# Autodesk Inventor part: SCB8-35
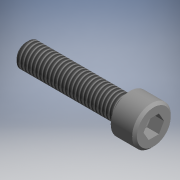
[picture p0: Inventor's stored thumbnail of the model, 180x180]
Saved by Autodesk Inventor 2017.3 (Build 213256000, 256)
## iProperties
Part Number: SCB8-35
Material: Generic
Catalog Web Link: www.cadenas.de
Description: SCB-Hexagon Socket Head Cap Screws - Stainless Steel
Vendor: MISUMI
Document SubType Name: Modeling
Designer: partserver
Manufacturer: MISUMI
Mass: 2.66941 g
Surface Area: 15.2394 cm^2
Volume: 2.66941 cm^3
Density: 1 g/cm^3
Appearance: PSOLRGB-175-175-175
Category: PARTsolutions
Company: MISUMI
Title: SCB8-35
Author: Cadenas PARTsolutions
Comments: Hexagon Socket Head Cap Screws - Stainless Steel
PSOL_IDENT_0: {$CADENAS_DATA\23d-libs\misumi\metric\27_screws_nuts\scb_fa.prj},154 {VTYP=3D},{NB=SCB8-35},{LINA=SC
PSOL_IDENT_1: B8-35},{NN=SCB},{DATE=03.06.2021 03:35:43},{GEOMDATE=23.02.2012 00:00:00},{VERSION=},{LINEID=110},{W
PSOL_IDENT_2: BVAR=L},{WBNUMERIC=L}  {NB=SCB8-35},{LINA=SCB8-35},{KT=DUMMY},{PN=SCB8-35},{MAT=SUSXM7(30430 Stainle
PSOL_IDENT_3: ss Steel)},{SC=A2-70},{M=8},{L=35},{LL=Full Thread},{L1=28},{TYPE=SCB},{M1=8.0},{L0=10,12,14,15,16,1
PSOL_IDENT_4: 8,20,22,25,30,35,40,45,50,55,60,65,70,75,80},{MP=8x1.25},{P=1.25},{A=13.0},{E=8.0},{B=6.0},{V=0.80}
NB: SCB8-35
NN: SCB
NT: Hexagon Socket Head Cap Screws - Stainless Steel
NBSYN: $PN.
LINA: SCB8-35
CATALOG: Misumi
PN: SCB8-35
MAT: 302HQ Stainless Steel
SC: A2-70
M: 8
L: 35
LL: Full Thread
MP: 8x1.25
A: 13
E: 8
B: 6
SUPPLIER: MISUMI
ARTICLENO: SCB8-35
BOMINFO: SCB8-35
CREATOR: CADENAS GmbH
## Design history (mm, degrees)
sketch "Sketch_1"
  geometry: L1 (35, 0)-(-8, 0); L2 (-8, 0)-(-8, 5.7); L3 (-8, 5.7)-(-7.2, 6.5); L4 (-7.2, 6.5)-(0, 6.5); L5 (0, 6.5)-(0, 4); L6 (0, 4)-(34.233, 4); L7 (34.233, 4)-(35, 3.233); L8 (35, 3.233)-(35, 0); L9 (35, 0)-(-8, 0)
  constraints: 18 end point
revolve "Revolution1" sketch "Sketch_1" stored, may be unused: angle "d0" = 360 deg
thread "Thread1" dims "d1" = 33.75, "d2" = 1.25
sketch "Sketch2"
  geometry: 1 further point
hole "Hole1" sketch "Sketch2" at (0, 0) diameter "d3" = 6; stored, may be unused: countersink angle "d7" = 90 deg, drill point angle "d9" = 150 deg; dims "d4" = 6, "d5" = 4, "d6" = 2, "d8" = 4
sketch "Sketch_3"
  geometry: L1 (-3, -1.732)-(0, -3.464); L2 (0, -3.464)-(3, -1.732); L3 (3, -1.732)-(3, 1.732); L4 (3, 1.732)-(0, 3.464); L5 (0, 3.464)-(-3, 1.732); L6 (-3, 1.732)-(-3, -1.732)
  constraints: 12 end point
extrude "Extrusion1" cut sketch "Sketch_3" distance "d10" = 4; taper "d11" = 0 deg
node "bolt_XY"
node "bolt_YZ"
node "bolt_ZX"
node "bolt_X"
node "bolt_Y"
node "bolt_Z"
node "bolt_Center"
node "nut_XY"
node "nut_YZ"
node "nut_ZX"
node "nut_X"
node "nut_Y"
node "nut_Z"
node "nut_Center"
body "Solid1"
other parameters: "d12" = 0, "d13" = 0
